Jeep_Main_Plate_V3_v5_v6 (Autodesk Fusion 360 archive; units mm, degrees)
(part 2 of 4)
sketch "Sketch16" plane through (0, 0, 15) normal (0, 0, 1) x axis (-1, 0, 0)
  line L1 (-8.4377, 5.259) -> (-11.4211, -2.2)
  line L2 (-10.5895, 5.2816) -> (-8.4377, 5.259)
  line L3 (2.418, 37.7236) -> (-10.5895, 5.2816)
  line L4 (3.9887, 36.2589) -> (2.418, 37.7236)
  line L5 (6.268, 41.9437) -> (3.9887, 36.2589)
  line L6 (18.9812, 36.8463) -> (6.268, 41.9437)
  line L7 (19.7255, 38.7027) -> (18.9812, 36.8463)
  line L8 (7.0123, 43.8) -> (19.7255, 38.7027)
  line L9 (-5, 43.8) -> (7.0123, 43.8)
  line L10 (-5, 42.6) -> (-5, 43.8)
  line L11 (0, 42.6) -> (-5, 42.6)
  line L12 (-57.3, 0) -> (-43.8, 0)
  line L13 (-60.8, 11) -> (-60.8, 3.5)
  line L14 (-62, 11) -> (-60.8, 11)
  line L15 (-62, 0.8) -> (-62, 11)
  line L16 (-11.4211, -2.2) -> (-59, -2.2)
  arc A1 centre (-49.0833, 49.2491) radius 49.5316 clockwise from (0, 42.6) to (-43.8, 0)
  arc A2 centre (-54.6577, 6.1423) radius 6.6865 clockwise from (-57.3, 0) to (-60.8, 3.5)
  arc A3 centre (-59, 0.8) radius 3 clockwise from (-59, -2.2) to (-62, 0.8)
extrude "Extrude16" cut of existing geometry blind -0.9
sketch "Sketch17" plane through (0, 0, 15) normal (0, 0, 1) x axis (-1, 0, 0)
  line L1 (-8.4377, 5.259) -> (-11.4211, -2.2)
  line L2 (-10.5895, 5.2816) -> (-8.4377, 5.259)
  line L3 (2.418, 37.7236) -> (-10.5895, 5.2816)
  line L4 (3.9887, 36.2589) -> (2.418, 37.7236)
  line L5 (6.268, 41.9437) -> (3.9887, 36.2589)
  line L6 (18.9812, 36.8463) -> (6.268, 41.9437)
  line L7 (19.7255, 38.7027) -> (18.9812, 36.8463)
  line L8 (7.0123, 43.8) -> (19.7255, 38.7027)
  line L9 (-5, 43.8) -> (7.0123, 43.8)
  line L10 (-5, 42.6) -> (-5, 43.8)
  line L11 (0, 42.6) -> (-5, 42.6)
  line L12 (-57.3, 0) -> (-43.8, 0)
  line L13 (-60.8, 11) -> (-60.8, 3.5)
  line L14 (-62, 11) -> (-60.8, 11)
  line L15 (-62, 0.8) -> (-62, 11)
  line L16 (-11.4211, -2.2) -> (-59, -2.2)
  arc A1 centre (-49.0833, 49.2491) radius 49.5316 clockwise from (0, 42.6) to (-43.8, 0)
  arc A2 centre (-54.6577, 6.1423) radius 6.6865 clockwise from (-57.3, 0) to (-60.8, 3.5)
  arc A3 centre (-59, 0.8) radius 3 clockwise from (-59, -2.2) to (-62, 0.8)
sketch "Sketch18" plane through (0, 0, 12) normal (0, 0, 1) x axis (-1, 0, 0)
  line L1 (2.7445, 0.6498) -> (17.4961, 37.4418)
  line L2 (3.9296, 0.6498) -> (2.7445, 0.6498)
  line L3 (4.3937, 0.4637) -> (3.9296, 0.6498)
  line L4 (18.9812, 36.8463) -> (4.3937, 0.4637)
  line L5 (17.4961, 37.4418) -> (18.9812, 36.8463)
  line L6 (10.0532, 18.8783) -> (17.4961, 37.4418)
  line L7 (15.3685, 18.8783) -> (10.0532, 18.8783)
  point P2 (17.4961, 37.4418)
  point P7 (17.4961, 37.4418)
  point P8 (10.0532, 18.8783)
  coincident P2 P7
  horizontal L7
  dimension "d118" distance P7 P8 = 20
extrude "Extrude17" cut sketch "Sketch18" profile of L1 L2 L3 L4 L7 against normal blind 10
sketch "Sketch19" plane through (0, 0, 2) normal (0, 0, 1) x axis (-1, 0, 0)
  line L1 (6.268, 41.9437) -> (17.4961, 37.4418)
  line L2 (3.9887, 36.2589) -> (6.268, 41.9437)
  line L3 (2.418, 37.7236) -> (3.9887, 36.2589)
  line L4 (-10.5895, 5.2816) -> (2.418, 37.7236)
  line L5 (-8.4377, 5.259) -> (-10.5895, 5.2816)
  line L6 (-11.4211, -2.2) -> (-8.4377, 5.259)
  line L7 (4.3937, 0.4637) -> (3.9296, 0.6498)
  line L8 (11.777, 18.8783) -> (4.3937, 0.4637)
  line L9 (10.0532, 18.8783) -> (11.777, 18.8783)
  line L10 (17.4961, 37.4418) -> (10.0532, 18.8783)
  arc A1 centre (-11.4211, 40.5698) radius 42.7698 clockwise from (3.9296, 0.6498) to (-11.4211, -2.2)
  arc A2 centre (-10.5418, 20.0938) radius 22.3111 clockwise from (6.4823, 5.6727) to (-11.4211, -2.2)
  point P15 (6.4823, 5.6727)
  point P8 (-11.4211, -2.2)
  point P14 (-11.4211, -2.2)
  coincident L8 P15
  coincident P8 P14
extrude "Extrude18" cut sketch "Sketch19" profile of A1 L7 L8 A2 against normal blind 10
fillet "Fillet3" radius 3
fillet "Fillet4" radius 4
fillet "Fillet5" radius 2
fillet "Fillet6" radius 7.25
sketch "Sketch20" plane through (0, 0, 2) normal (0, 0, 1) x axis (-1, 0, 0)
  line L1 (11.777, 18.8783) -> (6.4823, 5.6727)
  line L2 (10.0532, 18.8783) -> (11.777, 18.8783)
  line L3 (17.4961, 37.4418) -> (10.0532, 18.8783)
  line L4 (6.268, 41.9437) -> (17.4961, 37.4418)
  line L5 (3.9887, 36.2589) -> (6.268, 41.9437)
  line L6 (2.418, 37.7236) -> (3.9887, 36.2589)
  line L7 (-10.5895, 5.2816) -> (2.418, 37.7236)
  line L8 (-8.4377, 5.259) -> (-10.5895, 5.2816)
  line L9 (-10.4154, 0.3145) -> (-8.4377, 5.259)
  line L10 (-11.4211, -2.2) -> (-14.1293, -2.2)
  line L11 (3.9887, 36.2589) -> (-8.4377, 5.259)
  arc A1 centre (-10.5418, 20.0938) radius 22.3111 clockwise from (6.4823, 5.6727) to (-7.7545, -2.0425)
  arc A2 centre (-14.1293, 1.8) radius 4 clockwise from (-10.4154, 0.3145) to (-14.1293, -2.2)
  arc A3 centre (-11.4211, 40.5698) radius 42.7698 clockwise from (-7.7545, -2.0425) to (-11.4211, -2.2)
  point P12 (-8.4377, 5.259)
  point P18 (-8.4377, 5.259)
  point P9 (3.9887, 36.2589)
  point P19 (3.9887, 36.2589)
  coincident P12 P18
  coincident P9 P19
extrude "Extrude19" new body sketch "Sketch20" profile of L6 L7 L8 L11 along normal blind 13
sketch "Sketch21" plane through (0, 0, 15) normal (0, 0, 1) x axis (-1, 0, 0)
  line L1 (3.9887, 36.2589) -> (-8.4377, 5.259)
  line L2 (2.418, 37.7236) -> (3.9887, 36.2589)
  line L3 (-10.5895, 5.2816) -> (2.418, 37.7236)
  line L4 (-8.4377, 5.259) -> (-10.5895, 5.2816)
move "Move2"
sketch "Sketch22" plane through (0, 0, 34) normal (0, 0, 1) x axis (-1, 0, 0)
  line L1 (3.9887, 36.2589) -> (-8.4377, 5.259)
  line L2 (2.418, 37.7236) -> (3.9887, 36.2589)
  line L3 (-10.5895, 5.2816) -> (2.418, 37.7236)
  line L4 (-8.4377, 5.259) -> (-10.5895, 5.2816)
sketch "Sketch23" plane through (0, 0, 34) normal (0, 0, 1) x axis (-1, 0, 0)
  line L1 (3.9887, 36.2589) -> (-8.4377, 5.259)
  line L2 (2.418, 37.7236) -> (3.9887, 36.2589)
  line L3 (-10.5895, 5.2816) -> (2.418, 37.7236)
  line L4 (-8.4377, 5.259) -> (-10.5895, 5.2816)
  line L5 (7.0123, 49.1821) -> (1.6236, 35.7422)
  line L6 (18.9812, 36.8463) -> (6.268, 41.9437)
  line L7 (17.4961, 37.4418) -> (6.268, 41.9437)
  line L8 (4.4089, 42.689) -> (7.6114, 41.405)
  line L9 (6.268, 41.9437) -> (3.9887, 36.2589)
  line L10 (-15.0954, -5.9565) -> (-9.5797, 7.8002)
  line L11 (-12.7752, -5.5616) -> (-7.2156, 8.308)
  line L12 (-6.614, -0.9257) -> (-12.183, 1.3072)
  point P6 (1.6236, 35.7422)
  point P12 (7.6114, 41.405)
  point P13 (4.4089, 42.689)
  point P3 (3.9887, 36.2589)
  point P14 (3.9887, 36.2589)
  point P8 (6.268, 41.9437)
  point P15 (6.268, 41.9437)
  point P16 (-9.5797, 7.8002)
  point P18 (-7.2156, 8.308)
  point P20 (-12.183, 1.3072)
  point P21 (-6.614, -0.9257)
  coincident L3 P6
  parallel L3 L5
  coincident L6 P12
  coincident L5 P13
  perpendicular L5 L8
  coincident P3 P14
  coincident P8 P15
  coincident L3 P16
  parallel L3 L10
  coincident L1 P18
  parallel L1 L11
  coincident L10 P20
  dimension "d129" distance P20 P21 = 6
extrude "Extrude20" add sketch "Sketch23" profile of L1 L2 L3 L4 L5 L8 L9 L10 L11 L12 along normal blind 40
sketch "Sketch24" plane through (0, 0, 74) normal (0, 0, 1) x axis (-1, 0, 0)
  line L1 (-12.183, 1.3072) -> (4.4089, 42.689)
  line L2 (-10.3211, 0.5606) -> (-12.183, 1.3072)
  line L3 (3.9887, 36.2589) -> (-10.3211, 0.5606)
  line L4 (6.268, 41.9437) -> (3.9887, 36.2589)
  line L5 (4.4089, 42.689) -> (6.268, 41.9437)
remove_body "RemoveBody1"
sketch "Sketch25" plane through (0, 0, 2) normal (0, 0, 1) x axis (-1, 0, 0)
  line L1 (11.777, 18.8783) -> (6.4823, 5.6727)
  line L2 (10.0532, 18.8783) -> (11.777, 18.8783)
  line L3 (17.4961, 37.4418) -> (10.0532, 18.8783)
  line L4 (6.268, 41.9437) -> (17.4961, 37.4418)
  line L5 (3.9887, 36.2589) -> (6.268, 41.9437)
  line L6 (2.418, 37.7236) -> (3.9887, 36.2589)
  line L7 (-10.5895, 5.2816) -> (2.418, 37.7236)
  line L8 (-8.4377, 5.259) -> (-10.5895, 5.2816)
  line L9 (-10.4154, 0.3145) -> (-8.4377, 5.259)
  line L10 (-11.4211, -2.2) -> (-14.1293, -2.2)
  line L11 (-8.4377, 5.259) -> (-11.4211, -2.2)
  line L12 (8.3111, 47.134) -> (-9.9294, 1.5295)
  line L13 (3.9887, 36.2589) -> (-10.3211, 0.5606)
  line L14 (3.9887, 36.2589) -> (-8.4377, 5.259)
  line L15 (-11.7486, -3.0312) -> (-6.1781, 10.8961)
  line L16 (-25.6775, -38.0332) -> (7.6802, 45.5567)
  arc A1 centre (-10.5418, 20.0938) radius 22.3111 clockwise from (6.4823, 5.6727) to (-7.7545, -2.0425)
  arc A2 centre (-14.1293, 1.8) radius 4 clockwise from (-10.4154, 0.3145) to (-14.1293, -2.2)
  arc A3 centre (-11.4211, 40.5698) radius 42.7698 clockwise from (-7.7545, -2.0425) to (-11.4211, -2.2)
  point P20 (-9.9294, 1.5295)
  point P26 (-6.1781, 10.8961)
  point P28 (7.6802, 45.5567)
  point P27 (-11.7486, -3.0312)
  point P29 (-25.6775, -38.0332)
  midpoint L11 P20
  coincident L13 P26
  coincident L12 P28
  dimension "d132" distance P26 P27 = 15
  dimension "d133" distance P28 P29 = 90
split "Split1"
move "Move3"
sketch "Sketch26" plane through (0, 0, 0) normal (0, 1, 0) x axis (1, 0, 0)
  line L1 (-8.7, 0) -> (-4.2, 0)
  horizontal L1
sketch "Sketch27" plane through (0, 0, 0) normal (0, 0, 1) x axis (1, 0, 0)
  line L1 (-13.3689, -43.8) -> (-4.6131, -43.8)
  line L2 (-13.3689, -41.9403) -> (-13.3689, -43.8)
  line L3 (-4.6131, -41.9403) -> (-13.3689, -41.9403)
  line L4 (-4.6131, -43.8) -> (-4.6131, -41.9403)
  line L5 (5, -43.8) -> (-7.0123, -43.8)
  line L6 (5, -43.8) -> (-5.613, -43.8)
  point P2 (-4.6131, -43.8)
  horizontal L1
  vertical L2
  horizontal L3
  vertical L4
  coincident P2 L5
move "Move4"
sketch "Sketch28" plane through (0, 0, 2) normal (0, 0, 1) x axis (-1, 0, 0)
  line L1 (3.9749, 36.2718) -> (-11.3778, -2.2)
  line L2 (2.418, 37.7236) -> (3.9749, 36.2718)
  line L3 (-10.5895, 5.2816) -> (2.418, 37.7236)
  line L4 (-8.4377, 5.259) -> (-10.5895, 5.2816)
  line L5 (-10.4154, 0.3145) -> (-8.4377, 5.259)
  line L6 (-11.4211, -2.2) -> (-14.1293, -2.2)
  arc A1 centre (-14.1293, 1.8) radius 4 clockwise from (-10.4154, 0.3145) to (-14.1293, -2.2)
  arc A2 centre (-11.4211, 40.5698) radius 42.7698 clockwise from (-11.3778, -2.2) to (-11.4211, -2.2)
sketch "Sketch29" plane through (0, 0, 0) normal (0, 0, 1) x axis (1, 0, 0)
  line L1 (-17.0909, -43.8) -> (-4.2862, -43.8)
  line L2 (-17.0909, -41.9413) -> (-17.0909, -43.8)
  line L3 (-4.2862, -41.9413) -> (-17.0909, -41.9413)
  line L4 (-4.2862, -43.8) -> (-4.2862, -41.9413)
  line L5 (5, -43.8) -> (-5.613, -43.8)
  line L6 (-5.613, -43.8) -> (5, -43.8)
  line L7 (-17.8562, -43.8) -> (-3.9146, -43.8)
  line L8 (-17.8562, -41.9413) -> (-17.8562, -43.8)
  line L9 (-3.9146, -41.9413) -> (-17.8562, -41.9413)
  line L10 (-3.9146, -43.8) -> (-3.9146, -41.9413)
  point P2 (-4.2862, -43.8)
  point P10 (-3.9146, -43.8)
  horizontal L1
  vertical L2
  horizontal L3
  vertical L4
  coincident P2 L5
  horizontal L7
  vertical L8
  horizontal L9
  vertical L10
  coincident L5 P10
sketch "Sketch30" plane through (0, 0, 0) normal (0, 0, 1) x axis (1, 0, 0)
extrude "Extrude21" add sketch "Sketch29" profile of L1 L2 L3 L4 L5 L6 L7 L9 along normal blind 15
sketch "Sketch31" plane through (0, 0, 0) normal (0, 0, 1) x axis (1, 0, 0)
  line L1 (-2.418, -37.7236) -> (-3.9887, -36.2589)
  line L2 (-3.9887, -36.2589) -> (-2.418, -37.7236)
  line L3 (-14.5557, -26.4051) -> (-3.5854, -36.6351)
  line L4 (-15.267, -41.9413) -> (-10.534, -30.1553)
  line L5 (-6.268, -41.9437) -> (-15.267, -41.9413)
  line L6 (-3.9887, -36.2589) -> (-6.268, -41.9437)
  point P6 (-3.5854, -36.6351)
  point P9 (-10.534, -30.1553)
  point P8 (-15.267, -41.9413)
  point P10 (-15.267, -41.9413)
  point P11 (-6.268, -41.9437)
  point P12 (-6.268, -41.9437)
  point P5 (-3.9887, -36.2589)
  point P13 (-3.9887, -36.2589)
  point P7 (-14.5557, -26.4051)
  coincident L1 P6
  coincident L3 P9
  coincident P8 P10
  coincident P11 P12
  coincident P5 P13
  dimension "d136" distance P6 P7 = 15
extrude "Extrude22" add sketch "Sketch31" profile of L3 L4 L5 L6 along normal blind 15
sketch "Sketch32" plane through (0, 0, 0) normal (0, 0, 1) x axis (1, 0, 0)
  line L1 (10.5895, -5.2816) -> (8.4377, -5.259)
  line L2 (8.4377, -5.259) -> (10.5895, -5.2816)
  line L3 (-4.0781, -5.259) -> (9.8776, -5.2741)
  line L4 (2.3778, 2.2) -> (-0.6003, -5.2628)
  line L5 (59, 2.2) -> (11.4211, 2.2)
  line L6 (14.5973, 2.2) -> (2.3778, 2.2)
  line L7 (10.5895, -5.2816) -> (14.5973, 2.2)
  point P6 (9.8776, -5.2741)
  point P9 (-0.6003, -5.2628)
  point P8 (2.3778, 2.2)
  point P10 (2.3778, 2.2)
  point P13 (14.5973, 2.2)
  point P4 (10.5895, -5.2816)
  point P14 (10.5895, -5.2816)
  coincident L1 P6
  coincident L3 P9
  coincident P8 P10
  coincident L5 P13
  coincident P4 P14
extrude "Extrude23" add sketch "Sketch32" along normal blind 15
sketch "Sketch33" plane through (0, 0, 15) normal (0, 0, 1) x axis (-1, 0, 0)
  line L1 (2.418, 37.7236) -> (-10.5895, 5.2816)
  line L2 (3.9749, 36.2718) -> (2.418, 37.7236)
  line L3 (6.2374, 41.9413) -> (3.9749, 36.2718)
  line L4 (6.267, 41.9413) -> (6.2374, 41.9413)
  line L5 (3.9887, 36.2589) -> (6.267, 41.9413)
  line L6 (10.534, 30.1553) -> (3.9887, 36.2589)
  line L7 (12.9861, 36.2614) -> (10.534, 30.1553)
  line L8 (12.9887, 36.2589) -> (12.9861, 36.2614)
  line L9 (15.267, 41.9413) -> (12.9887, 36.2589)
  line L10 (15.274, 41.9413) -> (15.267, 41.9413)
  line L11 (27.9812, 36.8463) -> (15.274, 41.9413)
  line L12 (17.3111, 43.2793) -> (26.8692, 39.447)
  line L13 (17.0909, 43.8) -> (17.0909, 43.3634)
  line L14 (-5, 43.8) -> (17.0909, 43.8)
  line L15 (-5, 42.6) -> (-5, 43.8)
  line L16 (0, 42.6) -> (-5, 42.6)
  line L17 (-57.3, 0) -> (-43.8, 0)
  line L18 (-60.8, 11) -> (-60.8, 3.5)
  line L19 (-62, 11) -> (-60.8, 11)
  line L20 (-62, 0.8) -> (-62, 11)
  line L21 (-14.1293, -2.2) -> (-59, -2.2)
  line L22 (-2.3778, -2.2) -> (-14.1293, -2.2)
  line L23 (0.6003, 5.2628) -> (-2.3778, -2.2)
  line L24 (-9.8776, 5.2741) -> (0.6003, 5.2628)
  line L25 (-10.5895, 5.2816) -> (-9.8776, 5.2741)
  line L26 (9.0671, 46.5544) -> (18.3592, 42.859)
  arc A1 centre (26.1249, 37.5906) radius 2 clockwise from (26.8692, 39.447) to (27.9812, 36.8463)
  arc A2 centre (14.613, 36.55) radius 7.25 clockwise from (17.0909, 43.3634) to (17.3111, 43.2793)
  arc A3 centre (-49.0833, 49.2491) radius 49.5316 clockwise from (0, 42.6) to (-43.8, 0)
  arc A4 centre (-54.6577, 6.1423) radius 6.6865 clockwise from (-57.3, 0) to (-60.8, 3.5)
  arc A5 centre (-59, 0.8) radius 3 clockwise from (-59, -2.2) to (-62, 0.8)
  point P37 (18.3592, 42.859)
  point P38 (9.0671, 46.5544)
  coincident L12 P37
  dimension "d141" distance P37 P38 = 10
extrude "Extrude24" cut sketch "Sketch33" profile of L13 L14 L26 against normal blind 23.5
sketch "Sketch34" plane through (0, 0, 2) normal (0, 0, 1) x axis (-1, 0, 0)
  line L1 (10.534, 30.1553) -> (12.9861, 36.2614)
  line L2 (0.6003, 5.2628) -> (10.534, 30.1553)
  line L3 (-2.3778, -2.2) -> (0.6003, 5.2628)
  line L4 (20.777, 18.8783) -> (15.4823, 5.6727)
  line L5 (19.0532, 18.8783) -> (20.777, 18.8783)
  line L6 (26.4961, 37.4418) -> (19.0532, 18.8783)
  line L7 (15.274, 41.9413) -> (26.4961, 37.4418)
  line L8 (15.267, 41.9413) -> (15.274, 41.9413)
  line L9 (12.9887, 36.2589) -> (15.267, 41.9413)
  line L10 (12.9861, 36.2614) -> (12.9887, 36.2589)
  arc A1 centre (-2.4211, 40.5698) radius 42.7698 clockwise from (1.2455, -2.0425) to (-2.3778, -2.2)
  arc A2 centre (-1.5418, 20.0938) radius 22.3111 clockwise from (15.4823, 5.6727) to (1.2455, -2.0425)
fillet "Fillet7" radius 1
fillet "Fillet8" radius 8.5
sketch "Sketch35" plane through (0, 0, 0) normal (0, 0, 1) x axis (1, 0, 0)
  line L1 (-0.6003, -5.2628) -> (8.4377, -5.259)
  line L2 (-10.534, -30.1553) -> (-0.6003, -5.2628)
  line L3 (-3.9887, -36.2589) -> (-10.534, -30.1553)
  line L4 (8.4377, -5.259) -> (-3.9887, -36.2589)
  point P2 (8.4377, -5.259)
  point P4 (8.4377, -5.259)
  point P3 (-0.6003, -5.2628)
  point P5 (-0.6003, -5.2628)
  point P6 (-10.534, -30.1553)
  point P7 (-10.534, -30.1553)
  point P8 (-3.9887, -36.2589)
  point P9 (-3.9887, -36.2589)
  coincident P2 P4
  coincident P3 P5
  coincident P6 P7
  coincident P8 P9
extrude "Extrude25" add sketch "Sketch35" along normal blind 2
sketch "Sketch36" plane through (0, 0, 15) normal (0, 0, 1) x axis (-1, 0, 0)
  line L1 (-5, 43.8) -> (14.4017, 43.8)
  line L2 (-5, 42.6) -> (-5, 43.8)
  line L3 (0, 42.6) -> (-5, 42.6)
  line L4 (-57.3, 0) -> (-43.8, 0)
  line L5 (-60.8, 11) -> (-60.8, 3.5)
  line L6 (-62, 11) -> (-60.8, 11)
  line L7 (-62, 0.8) -> (-62, 11)
  line L8 (-14.1293, -2.2) -> (-59, -2.2)
  line L9 (-3.0554, -2.2) -> (-14.1293, -2.2)
  line L10 (0.6003, 5.2628) -> (-2.1266, -1.5706)
  line L11 (-9.8776, 5.2741) -> (0.6003, 5.2628)
  line L12 (-10.5895, 5.2816) -> (-9.8776, 5.2741)
  line L13 (2.418, 37.7236) -> (-10.5895, 5.2816)
  line L14 (3.9749, 36.2718) -> (2.418, 37.7236)
  line L15 (6.2374, 41.9413) -> (3.9749, 36.2718)
  line L16 (6.267, 41.9413) -> (6.2374, 41.9413)
  line L17 (3.9887, 36.2589) -> (6.267, 41.9413)
  line L18 (10.534, 30.1553) -> (3.9887, 36.2589)
  line L19 (12.9861, 36.2614) -> (10.534, 30.1553)
  line L20 (12.9887, 36.2589) -> (12.9861, 36.2614)
  line L21 (15.267, 41.9413) -> (12.9887, 36.2589)
  line L22 (15.274, 41.9413) -> (15.267, 41.9413)
  line L23 (27.9812, 36.8463) -> (15.274, 41.9413)
  line L24 (17.3111, 43.2793) -> (26.8692, 39.447)
  arc A1 centre (14.4017, 35.3) radius 8.5 clockwise from (14.4017, 43.8) to (17.0909, 43.3634)
  arc A2 centre (-49.0833, 49.2491) radius 49.5316 clockwise from (0, 42.6) to (-43.8, 0)
  arc A3 centre (-54.6577, 6.1423) radius 6.6865 clockwise from (-57.3, 0) to (-60.8, 3.5)
  arc A4 centre (-59, 0.8) radius 3 clockwise from (-59, -2.2) to (-62, 0.8)
  arc A5 centre (-3.0554, -1.2) radius 1 clockwise from (-2.1266, -1.5706) to (-3.0554, -2.2)
  arc A6 centre (26.1249, 37.5906) radius 2 clockwise from (26.8692, 39.447) to (27.9812, 36.8463)
  arc A7 centre (14.613, 36.55) radius 7.25 clockwise from (17.0909, 43.3634) to (17.3111, 43.2793)
sketch "Sketch37" plane through (0, 0, 15) normal (0, 0, 1) x axis (-1, 0, 0)
  line L1 (-5, 43.8) -> (14.4017, 43.8)
  line L2 (-5, 42.6) -> (-5, 43.8)
  line L3 (0, 42.6) -> (-5, 42.6)
  line L4 (-57.3, 0) -> (-43.8, 0)
  line L5 (-60.8, 11) -> (-60.8, 3.5)
  line L6 (-62, 11) -> (-60.8, 11)
  line L7 (-62, 0.8) -> (-62, 11)
  line L8 (-14.1293, -2.2) -> (-59, -2.2)
  line L9 (-3.0554, -2.2) -> (-14.1293, -2.2)
  line L10 (0.6003, 5.2628) -> (-2.1266, -1.5706)
  line L11 (-9.8776, 5.2741) -> (0.6003, 5.2628)
  line L12 (-10.5895, 5.2816) -> (-9.8776, 5.2741)
  line L13 (2.418, 37.7236) -> (-10.5895, 5.2816)
  line L14 (3.9749, 36.2718) -> (2.418, 37.7236)
  line L15 (6.2374, 41.9413) -> (3.9749, 36.2718)
  line L16 (6.267, 41.9413) -> (6.2374, 41.9413)
  line L17 (3.9887, 36.2589) -> (6.267, 41.9413)
  line L18 (10.534, 30.1553) -> (3.9887, 36.2589)
  line L19 (12.9861, 36.2614) -> (10.534, 30.1553)
  line L20 (12.9887, 36.2589) -> (12.9861, 36.2614)
  line L21 (15.267, 41.9413) -> (12.9887, 36.2589)
  line L22 (15.274, 41.9413) -> (15.267, 41.9413)
  line L23 (27.9812, 36.8463) -> (15.274, 41.9413)
  line L24 (17.3111, 43.2793) -> (26.8692, 39.447)
  arc A1 centre (14.4017, 35.3) radius 8.5 clockwise from (14.4017, 43.8) to (17.0909, 43.3634)
  arc A2 centre (-49.0833, 49.2491) radius 49.5316 clockwise from (0, 42.6) to (-43.8, 0)
  arc A3 centre (-54.6577, 6.1423) radius 6.6865 clockwise from (-57.3, 0) to (-60.8, 3.5)
  arc A4 centre (-59, 0.8) radius 3 clockwise from (-59, -2.2) to (-62, 0.8)
  arc A5 centre (-3.0554, -1.2) radius 1 clockwise from (-2.1266, -1.5706) to (-3.0554, -2.2)
  arc A6 centre (26.1249, 37.5906) radius 2 clockwise from (26.8692, 39.447) to (27.9812, 36.8463)
  arc A7 centre (14.613, 36.55) radius 7.25 clockwise from (17.0909, 43.3634) to (17.3111, 43.2793)
sketch "Sketch38" plane through (0, 0, 15) normal (0, 0, 1) x axis (-1, 0, 0)
  line L1 (-5, 43.8) -> (14.4017, 43.8)
  line L2 (-5, 42.6) -> (-5, 43.8)
  line L3 (0, 42.6) -> (-5, 42.6)
  line L4 (-57.3, 0) -> (-43.8, 0)
  line L5 (-60.8, 11) -> (-60.8, 3.5)
  line L6 (-62, 11) -> (-60.8, 11)
  line L7 (-62, 0.8) -> (-62, 11)
  line L8 (-14.1293, -2.2) -> (-59, -2.2)
  line L9 (-3.0554, -2.2) -> (-14.1293, -2.2)
  line L10 (0.6003, 5.2628) -> (-2.1266, -1.5706)
  line L11 (-9.8776, 5.2741) -> (0.6003, 5.2628)
  line L12 (-10.5895, 5.2816) -> (-9.8776, 5.2741)
  line L13 (2.418, 37.7236) -> (-10.5895, 5.2816)
  line L14 (3.9749, 36.2718) -> (2.418, 37.7236)
  line L15 (6.2374, 41.9413) -> (3.9749, 36.2718)
  line L16 (6.267, 41.9413) -> (6.2374, 41.9413)
  line L17 (3.9887, 36.2589) -> (6.267, 41.9413)
  line L18 (10.534, 30.1553) -> (3.9887, 36.2589)
  line L19 (12.9861, 36.2614) -> (10.534, 30.1553)
  line L20 (12.9887, 36.2589) -> (12.9861, 36.2614)
  line L21 (15.267, 41.9413) -> (12.9887, 36.2589)
  line L22 (15.274, 41.9413) -> (15.267, 41.9413)
  line L23 (27.9812, 36.8463) -> (15.274, 41.9413)
  line L24 (17.3111, 43.2793) -> (26.8692, 39.447)
  arc A1 centre (14.4017, 35.3) radius 8.5 clockwise from (14.4017, 43.8) to (17.0909, 43.3634)
  arc A2 centre (-49.0833, 49.2491) radius 49.5316 clockwise from (0, 42.6) to (-43.8, 0)
  arc A3 centre (-54.6577, 6.1423) radius 6.6865 clockwise from (-57.3, 0) to (-60.8, 3.5)
  arc A4 centre (-59, 0.8) radius 3 clockwise from (-59, -2.2) to (-62, 0.8)
  arc A5 centre (-3.0554, -1.2) radius 1 clockwise from (-2.1266, -1.5706) to (-3.0554, -2.2)
  arc A6 centre (26.1249, 37.5906) radius 2 clockwise from (26.8692, 39.447) to (27.9812, 36.8463)
  arc A7 centre (14.613, 36.55) radius 7.25 clockwise from (17.0909, 43.3634) to (17.3111, 43.2793)
sketch "Sketch39" plane through (10.9473, -4.3893, 0) normal (-0.9282, 0.3721, 0) x axis (-0.3721, -0.9282, 0)
  line L1 (35.9139, 2) -> (0.9613, 2)
  line L2 (35.9139, 15) -> (35.9139, 2)
  line L3 (0.9613, 15) -> (35.9139, 15)
  line L4 (0.9613, 2) -> (0.9613, 15)
sketch "Sketch40" plane through (0, 0, 15) normal (0, 0, 1) x axis (-1, 0, 0)
  line L1 (-5, 43.8) -> (14.4017, 43.8)
  line L2 (-5, 42.6) -> (-5, 43.8)
  line L3 (0, 42.6) -> (-5, 42.6)
  line L4 (-57.3, 0) -> (-43.8, 0)
  line L5 (-60.8, 11) -> (-60.8, 3.5)
  line L6 (-62, 11) -> (-60.8, 11)
  line L7 (-62, 0.8) -> (-62, 11)
  line L8 (-14.1293, -2.2) -> (-59, -2.2)
  line L9 (-3.0554, -2.2) -> (-14.1293, -2.2)
  line L10 (0.6003, 5.2628) -> (-2.1266, -1.5706)
  line L11 (-9.8776, 5.2741) -> (0.6003, 5.2628)
  line L12 (-10.5895, 5.2816) -> (-9.8776, 5.2741)
  line L13 (2.418, 37.7236) -> (-10.5895, 5.2816)
  line L14 (3.9749, 36.2718) -> (2.418, 37.7236)
  line L15 (6.2374, 41.9413) -> (3.9749, 36.2718)
  line L16 (6.267, 41.9413) -> (6.2374, 41.9413)
  line L17 (3.9887, 36.2589) -> (6.267, 41.9413)
  line L18 (10.534, 30.1553) -> (3.9887, 36.2589)
  line L19 (12.9861, 36.2614) -> (10.534, 30.1553)
  line L20 (12.9887, 36.2589) -> (12.9861, 36.2614)
  line L21 (15.267, 41.9413) -> (12.9887, 36.2589)
  line L22 (15.274, 41.9413) -> (15.267, 41.9413)
  line L23 (27.9812, 36.8463) -> (15.274, 41.9413)
  line L24 (17.3111, 43.2793) -> (26.8692, 39.447)
  arc A1 centre (14.4017, 35.3) radius 8.5 clockwise from (14.4017, 43.8) to (17.0909, 43.3634)
  arc A2 centre (-49.0833, 49.2491) radius 49.5316 clockwise from (0, 42.6) to (-43.8, 0)
  arc A3 centre (-54.6577, 6.1423) radius 6.6865 clockwise from (-57.3, 0) to (-60.8, 3.5)
  arc A4 centre (-59, 0.8) radius 3 clockwise from (-59, -2.2) to (-62, 0.8)
  arc A5 centre (-3.0554, -1.2) radius 1 clockwise from (-2.1266, -1.5706) to (-3.0554, -2.2)
  arc A6 centre (26.1249, 37.5906) radius 2 clockwise from (26.8692, 39.447) to (27.9812, 36.8463)
  arc A7 centre (14.613, 36.55) radius 7.25 clockwise from (17.0909, 43.3634) to (17.3111, 43.2793)
sketch "Sketch41" plane through (0, 0, 15) normal (0, 0, 1) x axis (-1, 0, 0)
  line L1 (-5, 43.8) -> (14.4017, 43.8)
  line L2 (-5, 42.6) -> (-5, 43.8)
  line L3 (0, 42.6) -> (-5, 42.6)
  line L4 (-57.3, 0) -> (-43.8, 0)
  line L5 (-60.8, 11) -> (-60.8, 3.5)
  line L6 (-62, 11) -> (-60.8, 11)
  line L7 (-62, 0.8) -> (-62, 11)
  line L8 (-14.1293, -2.2) -> (-59, -2.2)
  line L9 (-3.0554, -2.2) -> (-14.1293, -2.2)
  line L10 (0.6003, 5.2628) -> (-2.1266, -1.5706)
  line L11 (-9.8776, 5.2741) -> (0.6003, 5.2628)
  line L12 (-10.5895, 5.2816) -> (-9.8776, 5.2741)
  line L13 (2.418, 37.7236) -> (-10.5895, 5.2816)
  line L14 (3.9749, 36.2718) -> (2.418, 37.7236)
  line L15 (6.2374, 41.9413) -> (3.9749, 36.2718)
  line L16 (6.267, 41.9413) -> (6.2374, 41.9413)
  line L17 (3.9887, 36.2589) -> (6.267, 41.9413)
  line L18 (10.534, 30.1553) -> (3.9887, 36.2589)
  line L19 (12.9861, 36.2614) -> (10.534, 30.1553)
  line L20 (12.9887, 36.2589) -> (12.9861, 36.2614)
  line L21 (15.267, 41.9413) -> (12.9887, 36.2589)
  line L22 (15.274, 41.9413) -> (15.267, 41.9413)
  line L23 (27.9812, 36.8463) -> (15.274, 41.9413)
  line L24 (17.3111, 43.2793) -> (26.8692, 39.447)
  arc A1 centre (14.4017, 35.3) radius 8.5 clockwise from (14.4017, 43.8) to (17.0909, 43.3634)
  arc A2 centre (-49.0833, 49.2491) radius 49.5316 clockwise from (0, 42.6) to (-43.8, 0)
  arc A3 centre (-54.6577, 6.1423) radius 6.6865 clockwise from (-57.3, 0) to (-60.8, 3.5)
  arc A4 centre (-59, 0.8) radius 3 clockwise from (-59, -2.2) to (-62, 0.8)
  arc A5 centre (-3.0554, -1.2) radius 1 clockwise from (-2.1266, -1.5706) to (-3.0554, -2.2)
  arc A6 centre (26.1249, 37.5906) radius 2 clockwise from (26.8692, 39.447) to (27.9812, 36.8463)
  arc A7 centre (14.613, 36.55) radius 7.25 clockwise from (17.0909, 43.3634) to (17.3111, 43.2793)
sketch "Sketch42" plane through (0, 0, 15) normal (0, 0, 1) x axis (-1, 0, 0)
  line L1 (-5, 43.8) -> (14.4017, 43.8)
  line L2 (-5, 42.6) -> (-5, 43.8)
  line L3 (0, 42.6) -> (-5, 42.6)
  line L4 (-57.3, 0) -> (-43.8, 0)
  line L5 (-60.8, 11) -> (-60.8, 3.5)
  line L6 (-62, 11) -> (-60.8, 11)
  line L7 (-62, 0.8) -> (-62, 11)
  line L8 (-14.1293, -2.2) -> (-59, -2.2)
  line L9 (-3.0554, -2.2) -> (-14.1293, -2.2)
  line L10 (0.6003, 5.2628) -> (-2.1266, -1.5706)
  line L11 (-9.8776, 5.2741) -> (0.6003, 5.2628)
  line L12 (-10.5895, 5.2816) -> (-9.8776, 5.2741)
  line L13 (2.418, 37.7236) -> (-10.5895, 5.2816)
  line L14 (3.9749, 36.2718) -> (2.418, 37.7236)
  line L15 (6.2374, 41.9413) -> (3.9749, 36.2718)
  line L16 (6.267, 41.9413) -> (6.2374, 41.9413)
  line L17 (3.9887, 36.2589) -> (6.267, 41.9413)
  line L18 (10.534, 30.1553) -> (3.9887, 36.2589)
  line L19 (12.9861, 36.2614) -> (10.534, 30.1553)
  line L20 (12.9887, 36.2589) -> (12.9861, 36.2614)
  line L21 (15.267, 41.9413) -> (12.9887, 36.2589)
  line L22 (15.274, 41.9413) -> (15.267, 41.9413)
  line L23 (27.9812, 36.8463) -> (15.274, 41.9413)
  line L24 (17.3111, 43.2793) -> (26.8692, 39.447)
  arc A1 centre (14.4017, 35.3) radius 8.5 clockwise from (14.4017, 43.8) to (17.0909, 43.3634)
  arc A2 centre (-49.0833, 49.2491) radius 49.5316 clockwise from (0, 42.6) to (-43.8, 0)
  arc A3 centre (-54.6577, 6.1423) radius 6.6865 clockwise from (-57.3, 0) to (-60.8, 3.5)
  arc A4 centre (-59, 0.8) radius 3 clockwise from (-59, -2.2) to (-62, 0.8)
  arc A5 centre (-3.0554, -1.2) radius 1 clockwise from (-2.1266, -1.5706) to (-3.0554, -2.2)
  arc A6 centre (26.1249, 37.5906) radius 2 clockwise from (26.8692, 39.447) to (27.9812, 36.8463)
  arc A7 centre (14.613, 36.55) radius 7.25 clockwise from (17.0909, 43.3634) to (17.3111, 43.2793)
sketch "Sketch43" plane through (0, 0, 15) normal (0, 0, 1) x axis (-1, 0, 0)
  line L1 (-5, 43.8) -> (14.4017, 43.8)
  line L2 (-5, 42.6) -> (-5, 43.8)
  line L3 (0, 42.6) -> (-5, 42.6)
  line L4 (-57.3, 0) -> (-43.8, 0)
  line L5 (-60.8, 11) -> (-60.8, 3.5)
  line L6 (-62, 11) -> (-60.8, 11)
  line L7 (-62, 0.8) -> (-62, 11)
  line L8 (-14.1293, -2.2) -> (-59, -2.2)
  line L9 (-3.0554, -2.2) -> (-14.1293, -2.2)
  line L10 (0.6003, 5.2628) -> (-2.1266, -1.5706)
  line L11 (-9.8776, 5.2741) -> (0.6003, 5.2628)
  line L12 (-10.5895, 5.2816) -> (-9.8776, 5.2741)
  line L13 (2.418, 37.7236) -> (-10.5895, 5.2816)
  line L14 (3.9749, 36.2718) -> (2.418, 37.7236)
  line L15 (6.2374, 41.9413) -> (3.9749, 36.2718)
  line L16 (6.267, 41.9413) -> (6.2374, 41.9413)
  line L17 (3.9887, 36.2589) -> (6.267, 41.9413)
  line L18 (10.534, 30.1553) -> (3.9887, 36.2589)
  line L19 (12.9861, 36.2614) -> (10.534, 30.1553)
  line L20 (12.9887, 36.2589) -> (12.9861, 36.2614)
  line L21 (15.267, 41.9413) -> (12.9887, 36.2589)
  line L22 (15.274, 41.9413) -> (15.267, 41.9413)
  line L23 (27.9812, 36.8463) -> (15.274, 41.9413)
  line L24 (17.3111, 43.2793) -> (26.8692, 39.447)
  line L25 (5.1224, 5.2741) -> (-9.8776, 5.2741)
  line L26 (11.5275, 20.7345) -> (2.418, 37.7236)
  line L27 (21.6953, 37.7236) -> (2.418, 37.7236)
  line L28 (6.7923, 10.9964) -> (-10.5895, 5.2816)
  line L29 (7.7077, 5.2816) -> (-10.5895, 5.2816)
  line L30 (-0.7632, 1.8461) -> (12.4608, 34.9534)
  arc A1 centre (14.4017, 35.3) radius 8.5 clockwise from (14.4017, 43.8) to (17.0909, 43.3634)
  arc A2 centre (-49.0833, 49.2491) radius 49.5316 clockwise from (0, 42.6) to (-43.8, 0)
  arc A3 centre (-54.6577, 6.1423) radius 6.6865 clockwise from (-57.3, 0) to (-60.8, 3.5)
  arc A4 centre (-59, 0.8) radius 3 clockwise from (-59, -2.2) to (-62, 0.8)
  arc A5 centre (-3.0554, -1.2) radius 1 clockwise from (-2.1266, -1.5706) to (-3.0554, -2.2)
  arc A6 centre (26.1249, 37.5906) radius 2 clockwise from (26.8692, 39.447) to (27.9812, 36.8463)
  arc A7 centre (14.613, 36.55) radius 7.25 clockwise from (17.0909, 43.3634) to (17.3111, 43.2793)
  point P23 (-9.8776, 5.2741)
  point P40 (-9.8776, 5.2741)
  point P25 (2.418, 37.7236)
  point P42 (2.418, 37.7236)
  point P24 (-10.5895, 5.2816)
  point P45 (-10.5895, 5.2816)
  point P48 (12.4608, 34.9534)
  point P49 (-0.7632, 1.8461)
  coincident P23 P40
  horizontal L25
  coincident P25 P42
  horizontal L27
  coincident P24 P45
  horizontal L29
  coincident L19 P48
  midpoint L10 P49
  dimension "d150" angle L26 L27 = 61.8
  dimension "d151" angle L28 L29 = 18.2
extrude "Extrude26" add sketch "Sketch43" profile of L10 L11 L12 L14 L15 L16 L17 L18 L19 L26 L28 L30 against normal blind 13.5
sketch "Sketch44" plane through (0, 0, 15) normal (0, 0, 1) x axis (-1, 0, 0)
  line L1 (-5, 43.8) -> (14.4017, 43.8)
  line L2 (-5, 42.6) -> (-5, 43.8)
  line L3 (0, 42.6) -> (-5, 42.6)
  line L4 (-57.3, 0) -> (-43.8, 0)
  line L5 (-60.8, 11) -> (-60.8, 3.5)
  line L6 (-62, 11) -> (-60.8, 11)
  line L7 (-62, 0.8) -> (-62, 11)
  line L8 (-14.1293, -2.2) -> (-59, -2.2)
  line L9 (-3.0554, -2.2) -> (-14.1293, -2.2)
  line L10 (-0.7632, 1.8461) -> (-2.1266, -1.5706)
  line L11 (2.3021, 9.5201) -> (-0.7632, 1.8461)
  line L12 (-10.5895, 5.2816) -> (2.3021, 9.5201)
  line L13 (2.418, 37.7236) -> (-10.5895, 5.2816)
  line L14 (8.8076, 25.8072) -> (2.418, 37.7236)
  line L15 (12.4608, 34.9534) -> (8.8076, 25.8072)
  line L16 (12.9861, 36.2614) -> (12.4608, 34.9534)
  line L17 (12.9887, 36.2589) -> (12.9861, 36.2614)
  line L18 (15.267, 41.9413) -> (12.9887, 36.2589)
  line L19 (15.274, 41.9413) -> (15.267, 41.9413)
  line L20 (27.9812, 36.8463) -> (15.274, 41.9413)
  line L21 (17.3111, 43.2793) -> (26.8692, 39.447)
  line L22 (-1.184, 48.54) -> (18.0582, 40.8249)
  arc A1 centre (14.4017, 35.3) radius 8.5 clockwise from (14.4017, 43.8) to (17.0909, 43.3634)
  arc A2 centre (-49.0833, 49.2491) radius 49.5316 clockwise from (0, 42.6) to (-43.8, 0)
  arc A3 centre (-54.6577, 6.1423) radius 6.6865 clockwise from (-57.3, 0) to (-60.8, 3.5)
  arc A4 centre (-59, 0.8) radius 3 clockwise from (-59, -2.2) to (-62, 0.8)
  arc A5 centre (-3.0554, -1.2) radius 1 clockwise from (-2.1266, -1.5706) to (-3.0554, -2.2)
  arc A6 centre (26.1249, 37.5906) radius 2 clockwise from (26.8692, 39.447) to (27.9812, 36.8463)
  arc A7 centre (14.613, 36.55) radius 7.25 clockwise from (17.0909, 43.3634) to (17.3111, 43.2793)
  point P37 (18.0582, 40.8249)
  coincident L20 P37
  parallel L20 L22
sketch "Sketch45" plane through (0, 0, 12) normal (0, 0, 1) x axis (-1, 0, 0)
  line L1 (21.9798, 21.8783) -> (20.256, 21.8783)
  line L2 (27.9812, 36.8463) -> (21.9798, 21.8783)
  line L3 (26.4961, 37.4418) -> (27.9812, 36.8463)
  line L4 (20.256, 21.8783) -> (26.4961, 37.4418)
delete_face "DeleteFace1"
extrude "Extrude27" add of existing geometry blind 1
fillet "Fillet9" radius 2
sketch "Sketch46" plane through (0, 0, 0) normal (0, 0, -1) x axis (1, 0, 0)
  line L1 (63, 11) -> (63, -0.2)
  line L2 (60.8, 11) -> (63, 11)
  line L3 (60.8, 3.5) -> (60.8, 11)
  line L4 (43.8, 0) -> (57.3, 0)
  line L5 (5, 42.6) -> (0, 42.6)
  line L6 (5, 43.8) -> (5, 42.6)
  line L7 (-14.4017, 43.8) -> (5, 43.8)
  line L8 (-26.8692, 39.447) -> (-17.3111, 43.2793)
  line L9 (-15.4823, 5.6727) -> (-27.9812, 36.8463)
  line L10 (11.4211, -2.2) -> (2.3778, -2.2)
  line L11 (61, -2.2) -> (11.4211, -2.2)
  line L12 (-6.267, 41.9413) -> (-3.9887, 36.2589)
  line L13 (-6.2374, 41.9413) -> (-6.267, 41.9413)
  arc A1 centre (61, -0.2) radius 2 clockwise from (63, -0.2) to (61, -2.2)
  arc A2 centre (54.6577, 6.1423) radius 6.6865 clockwise from (60.8, 3.5) to (57.3, 0)
  arc A3 centre (49.0833, 49.2491) radius 49.5316 clockwise from (43.8, 0) to (0, 42.6)
  arc A4 centre (-14.4017, 35.3) radius 8.5 clockwise from (-17.0909, 43.3634) to (-14.4017, 43.8)
  arc A5 centre (-14.613, 36.55) radius 7.25 clockwise from (-17.3111, 43.2793) to (-17.0909, 43.3634)
  arc A6 centre (-26.1249, 37.5906) radius 2 clockwise from (-27.9812, 36.8463) to (-26.8692, 39.447)
  arc A7 centre (1.5418, 20.0938) radius 22.3111 clockwise from (-1.2455, -2.0425) to (-15.4823, 5.6727)
  arc A8 centre (2.4211, 40.5698) radius 42.7698 clockwise from (2.3778, -2.2) to (-1.2455, -2.0425)
extrude "Extrude28" cut of existing geometry blind -2
delete_face "DeleteFace2"
delete_face "DeleteFace3"
extrude "Extrude29" add sketch "Sketch46" profile of A1 L1 L2 L3 A2 L4 A3 L5 L6 L7 A4 A5 L8 A6 L9 A7 A8 L10 L11 against normal blind 2
fillet "Fillet10" radius 1

design "Jeep_Right_Side_v2"
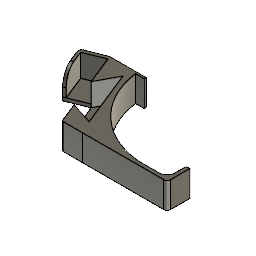
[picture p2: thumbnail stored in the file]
sketch "Sketch1" plane through (0, 0, 0) normal (0, 0, 1) x axis (1, 0, 0)
  line L1 (56, 0) -> (0, 0)
  line L2 (0, 1.2) -> (56, 1.2)
  line L3 (0, 0) -> (0, 1.2)
  line L4 (-1.2, 1.2) -> (0, 1.2)
  line L5 (-1.2, -43.8) -> (-1.2, 1.2)
  line L6 (0, -43.8) -> (-1.2, -43.8)
  line L7 (0, 1.2) -> (0, -43.8)
  line L8 (5, -43.8) -> (0, -43.8)
  line L9 (5, -42.6) -> (5, -43.8)
  line L10 (0, -42.6) -> (5, -42.6)
  line L11 (0, -43.8) -> (0, -42.6)
  line L12 (54.8, 0) -> (56, 0)
  line L13 (61, 1.2) -> (56, 1.2)
  line L14 (56, 0) -> (61, 0)
  line L15 (59.8, 0) -> (61, 0)
  line L16 (62, 1.2) -> (61, 1.2)
  line L17 (62, 0) -> (62, 1.2)
  line L18 (61, 0) -> (62, 0)
  line L19 (60.8, 0) -> (62, 0)
  line L20 (40.8, 0) -> (60.8, 0)
  line L21 (14.1421, -14.1421) -> (0, 0)
  line L22 (43.8, 0) -> (60.8, 0)
  line L23 (60.8, 0) -> (62, 0)
  line L24 (60.8, -13) -> (60.8, 0)
  line L25 (62, -13) -> (60.8, -13)
  line L26 (62, 0) -> (62, -13)
  line L27 (58.8, 0) -> (60.8, 0)
  line L28 (60.8, -2) -> (60.8, 0)
  line L29 (59.3858, -1.4142) -> (60.8, 0)
  line L30 (62.8, 0) -> (60.8, 0)
  line L31 (57.3, 0) -> (60.8, 0)
  line L32 (60.8, -3.5) -> (60.8, 0)
  line L33 (57.3, 0) -> (60.8, 0)
  line L34 (62, -11) -> (62, -13)
  line L35 (60.8, -11) -> (62, -11)
  arc A1 centre (49.0833, -49.2491) radius 49.5316 clockwise from (0, -42.6) to (43.8, 0)
  arc A2 centre (49.0833, -49.2491) radius 50.7316 clockwise from (-1.1891, -42.4389) to (43.672, 1.1932)
  arc A3 centre (54.6577, -6.1423) radius 6.6865 clockwise from (57.3, 0) to (60.8, -3.5)
  point P1 (0, 0)
  point P2 (0, 0)
  point P22 (0, 0)
  point P23 (14.1421, -14.1421)
  point P33 (60.8, -2)
  point P36 (57.3, 0)
  point P34 (59.3858, -1.4142)
  point P41 (60.8, -11)
  point P5 (0, 1.2)
  point P6 (-1.2, 1.2)
  point P8 (0, -43.8)
  point P9 (5, -43.8)
  point P11 (0, -42.6)
  point P13 (61, 1.2)
  point P17 (62, 1.2)
  point P20 (60.8, 0)
  point P24 (43.8, 0)
  point P18 (62, 0)
  point P31 (62, -13)
  point P29 (60.8, 0)
  point P37 (60.8, -3.5)
  point P38 (57.3, 0)
  point P40 (62, -11)
  horizontal L1
  horizontal L2
  vertical L3
  coincident P1 P2
  horizontal L4
  vertical L5
  horizontal L6
  vertical L7
  horizontal L8
  vertical L9
  horizontal L10
  vertical L11
  horizontal L12
  horizontal L13
  horizontal L14
  horizontal L15
  horizontal L16
  vertical L17
  horizontal L18
  horizontal L19
  coincident P1 P22
  coincident P23 A1
  horizontal L23
  vertical L24
  horizontal L25
  vertical L26
  coincident L24 P33
  perpendicular L18 L28
  horizontal L30
  coincident L14 P36
  coincident L22 P36
  coincident L20 P36
  coincident P34 A3
  coincident L24 P41
  perpendicular L24 L35
  dimension "d26" distance P2 P5 = 1.2
  dimension "d27" distance P5 P6 = 1.2
  dimension "d28" distance P5 P8 = 45
  dimension "d29" distance P8 P9 = 5
  dimension "d30" distance P8 P11 = 1.2
  dimension "d34" distance P13 P17 = 1
  dimension "d38" distance P22 P23 = 20
  dimension "d39" distance P20 P24 = 17
  dimension "d40" = 1.2
  dimension "d41" distance P18 P31 = 13
  dimension "d42" distance P18 P29 = 1.2
  dimension "d45" angle L29 L30 = 135
  dimension "d46" distance P29 P34 = 2
  dimension "d47" distance P20 P37 = 3.5
  dimension "d48" distance P29 P38 = 3.5
  dimension "d49" distance P31 P40 = 2
extrude "Extrude1" new body sketch "Sketch1" profile of L1 L2 L3 L4 L5 L6 L7 L8 L9 L10 L11 L12 L13 L14 L15 L16 L17 L18 L19 L20 L21 L22 A1 A2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 along normal blind 5
sketch "Sketch2" plane through (0, 0, 0) normal (0, 0, 1) x axis (1, 0, 0)
  line L1 (5, -43.8) -> (-1.2, -43.8)
  line L2 (36.9084, 0) -> (0, 0)
  line L3 (-3.5615, -43.8) -> (14.2717, 0)
  line L4 (-4.6753, -43.3534) -> (-3.5615, -43.8)
  line L5 (12.7071, 0) -> (-4.6753, -43.3534)
  line L6 (-1.2, -43.8) -> (-3.5615, -43.8)
  line L7 (-9.9836, -40.5566) -> (-4.6753, -43.3534)
  line L8 (-5.7884, -32.5942) -> (-9.9836, -40.5566)
  line L9 (-1.3079, -34.9548) -> (-5.7884, -32.5942)
  line L10 (9.3578, -8.3536) -> (12.7071, 0)
  line L11 (3.7888, -6.1207) -> (9.3578, -8.3536)
  line L12 (6.2428, 0) -> (3.7888, -6.1207)
  line L13 (-1.2, -38) -> (-1.2, -43.8)
  line L14 (-3.5615, -43.8) -> (-1.2, -38)
  point P7 (14.2717, 0)
  point P10 (12.7071, 0)
  point P3 (-1.2, -43.8)
  point P11 (-1.2, -43.8)
  point P14 (-1.3079, -34.9548)
  point P17 (6.2428, 0)
  point P18 (-1.2, -38)
  point P8 (-3.5615, -43.8)
  point P9 (-4.6753, -43.3534)
  point P12 (-9.9836, -40.5566)
  point P13 (-5.7884, -32.5942)
  point P15 (9.3578, -8.3536)
  point P16 (3.7888, -6.1207)
  coincident L2 P7
  coincident L2 P10
  perpendicular L4 L5
  coincident P3 P11
  parallel L1 L6
  coincident L5 P14
  perpendicular L8 L9
  coincident L2 P17
  perpendicular L11 L12
  coincident L3 P18
  perpendicular L1 L13
  dimension "d52" distance P8 P9 = 1.2
  dimension "d55" distance P9 P12 = 6
  dimension "d56" distance P12 P13 = 9
  dimension "d57" distance P10 P15 = 9
  dimension "d58" distance P15 P16 = 6
extrude "Extrude2" add sketch "Sketch2" profile of L2 L3 L4 L5 L6 L7 L8 L9 L10 L11 L12 L13 L14 along normal blind 15
extrude "Extrude3" add of existing geometry blind 10
sketch "Sketch3" plane through (0, 0, 15) normal (0, 0, 1) x axis (-1, 0, 0)
  line L1 (-14.2717, 0) -> (0, 35.0527)
  line L2 (-36.9084, 0) -> (-14.2717, 0)
  line L3 (0, 35.0527) -> (0, 36.4223)
  line L4 (-3.7888, 6.1207) -> (-6.2428, 0)
  line L5 (-9.3578, 8.3536) -> (-3.7888, 6.1207)
  line L6 (0, 31.6928) -> (-9.3578, 8.3536)
  line L7 (0, 0) -> (0, 31.6928)
  line L8 (-6.2428, 0) -> (0, 0)
  line L9 (-5, 43.8) -> (3.5615, 43.8)
  line L10 (-5, 42.6) -> (-5, 43.8)
  line L11 (0, 42.6) -> (-5, 42.6)
  line L12 (-57.3, 0) -> (-43.8, 0)
  line L13 (-60.8, 11) -> (-60.8, 3.5)
  line L14 (-62, 11) -> (-60.8, 11)
  line L15 (-62, -1.2) -> (-62, 11)
  line L16 (1.2, -1.2) -> (-62, -1.2)
  line L17 (1.2, 34.6857) -> (1.2, -1.2)
  line L18 (1.3079, 34.9548) -> (1.2, 34.6857)
  line L19 (5.7884, 32.5942) -> (1.3079, 34.9548)
  line L20 (9.9836, 40.5566) -> (5.7884, 32.5942)
  line L21 (4.6753, 43.3534) -> (9.9836, 40.5566)
  line L22 (3.5615, 43.8) -> (4.6753, 43.3534)
  line L23 (1.2, 34.6857) -> (0, 31.6928)
  line L24 (-7.3301, -2.7117) -> (-5.8415, 1.001)
  arc A1 centre (-49.0833, 49.2491) radius 50.7316 clockwise from (0, 36.4223) to (-36.9084, 0)
  arc A2 centre (-49.0833, 49.2491) radius 49.5316 clockwise from (0, 42.6) to (-43.8, 0)
  arc A3 centre (-54.6577, 6.1423) radius 6.6865 clockwise from (-57.3, 0) to (-60.8, 3.5)
  point P10 (0, 31.6928)
  point P29 (0, 31.6928)
  point P24 (1.2, 34.6857)
  point P30 (1.2, 34.6857)
  point P31 (-5.8415, 1.001)
  point P32 (-7.3301, -2.7117)
  coincident P10 P29
  coincident P24 P30
  coincident L4 P31
  dimension "d63" distance P31 P32 = 4
extrude "Extrude4" cut sketch "Sketch3" profile of L7 L8 L16 L17 L23 L24 against normal blind 19
sketch "Sketch4" plane through (0, 0, 0) normal (0, 0, 1) x axis (1, 0, 0)
sketch "Sketch5" plane through (0, 0, 0) normal (0, 0, 1) x axis (1, 0, 0)
  line L1 (36.9084, 0) -> (14.2717, 0)
  line L2 (36.9084, 0) -> (14.2717, 0)
  line L3 (0, -35.0527) -> (14.2717, 0)
  line L4 (0, -36.4223) -> (0, -35.0527)
  arc A1 centre (49.0833, -49.2491) radius 50.7316 clockwise from (0, -36.4223) to (36.9084, 0)
  arc A2 centre (49.0833, -49.2491) radius 50.7316 clockwise from (0, -36.4223) to (36.9084, 0)
  point P2 (14.2717, 0)
  point P6 (14.2717, 0)
  point P3 (36.9084, 0)
  point P7 (36.9084, 0)
  point P9 (36.9084, 0)
  point P8 (0, -36.4223)
  point P11 (0, -36.4223)
  point P14 (0, -35.0527)
  point P15 (0, -35.0527)
  point P12 (0, -36.4223)
  point P16 (0, -36.4223)
  coincident P2 P6
  coincident P3 P7
  coincident P3 P9
  coincident P8 P11
  coincident P14 P15
  coincident P12 P16
extrude "Extrude5" add sketch "Sketch5" along normal blind 15
sketch "Sketch6" plane through (0, 0, 0) normal (0, 0, 1) x axis (1, 0, 0)
extrude "Extrude6" add of existing geometry blind 1
fillet "Fillet1" radius 2.5
fillet "Fillet2" radius 3
sketch "Sketch7" plane through (0, 0, 15) normal (0, 0, 1) x axis (-1, 0, 0)
  line L1 (-8.724, -2.2) -> (-59, -2.2)
  line L2 (-3.7888, 6.1207) -> (-6.724, -1.2)
  line L3 (-9.3578, 8.3536) -> (-3.7888, 6.1207)
  line L4 (1.3079, 34.9548) -> (-9.3578, 8.3536)
  line L5 (5.7884, 32.5942) -> (1.3079, 34.9548)
  line L6 (9.9836, 40.5566) -> (5.7884, 32.5942)
  line L7 (4.6753, 43.3534) -> (9.9836, 40.5566)
  line L8 (3.5615, 43.8) -> (4.6753, 43.3534)
  line L9 (-5, 43.8) -> (3.5615, 43.8)
  line L10 (-5, 42.6) -> (-5, 43.8)
  line L11 (0, 42.6) -> (-5, 42.6)
  line L12 (-57.3, 0) -> (-43.8, 0)
  line L13 (-60.8, 11) -> (-60.8, 3.5)
  line L14 (-62, 11) -> (-60.8, 11)
  line L15 (-62, 0.8) -> (-62, 11)
  line L16 (-15.2943, -6.4527) -> (-7.555, 12.8499)
  line L17 (6.3033, 47.414) -> (-1.0507, 29.0723)
  arc A1 centre (-59, 0.8) radius 3 clockwise from (-59, -2.2) to (-62, 0.8)
  arc A2 centre (-8.724, 0.3) radius 2.5 clockwise from (-6.724, -1.2) to (-8.724, -2.2)
  arc A3 centre (-49.0833, 49.2491) radius 49.5316 clockwise from (0, 42.6) to (-43.8, 0)
  arc A4 centre (-54.6577, 6.1423) radius 6.6865 clockwise from (-57.3, 0) to (-60.8, 3.5)
  point P25 (-7.555, 12.8499)
  point P27 (-1.0507, 29.0723)
  coincident L4 P25
  parallel L4 L16
  coincident L4 P27
  parallel L4 L17
extrude "Extrude7" cut sketch "Sketch7" profile of L1 A2 L2 L3 L5 L6 L7 L16 L17 against normal blind 55
sketch "Sketch8" plane through (0, 0, 15) normal (0, 0, 1) x axis (-1, 0, 0)
  line L1 (4.6753, 43.3534) -> (-13.5892, -2.2)
  line L2 (3.5615, 43.8) -> (4.6753, 43.3534)
  line L3 (-5, 43.8) -> (3.5615, 43.8)
  line L4 (-5, 42.6) -> (-5, 43.8)
  line L5 (0, 42.6) -> (-5, 42.6)
  line L6 (-57.3, 0) -> (-43.8, 0)
  line L7 (-60.8, 11) -> (-60.8, 3.5)
  line L8 (-62, 11) -> (-60.8, 11)
  line L9 (-62, 0.8) -> (-62, 11)
  line L10 (-13.5892, -2.2) -> (-59, -2.2)
  line L11 (9.3161, 41.4927) -> (4.6753, 43.3534)
  line L12 (6.339, 34.0673) -> (9.3161, 41.4927)
  line L13 (1.9508, 38.1593) -> (6.339, 34.0673)
  line L14 (12.339, 34.0673) -> (6.339, 34.0673)
  line L15 (-9.142, -4.5438) -> (7.8275, 37.78)
  line L16 (-8.2023, -2.2) -> (-13.5892, -2.2)
  line L17 (-5.2251, 5.2254) -> (-8.2023, -2.2)
  line L18 (-12.6359, 5.303) -> (-5.2251, 5.2254)
  line L19 (2.1861, 5.2254) -> (-5.2251, 5.2254)
  line L20 (13, 43.8) -> (3.5615, 43.8)
  line L21 (11.1769, 46.1335) -> (9.3161, 41.4927)
  arc A1 centre (-49.0833, 49.2491) radius 49.5316 clockwise from (0, 42.6) to (-43.8, 0)
  arc A2 centre (-54.6577, 6.1423) radius 6.6865 clockwise from (-57.3, 0) to (-60.8, 3.5)
  arc A3 centre (-59, 0.8) radius 3 clockwise from (-59, -2.2) to (-62, 0.8)
  point P3 (4.6753, 43.3534)
  point P18 (4.6753, 43.3534)
  point P23 (7.8275, 37.78)
  point P2 (-13.5892, -2.2)
  point P25 (-13.5892, -2.2)
  point P26 (-8.2023, -2.2)
  point P4 (3.5615, 43.8)
  point P30 (3.5615, 43.8)
  point P19 (9.3161, 41.4927)
  point P20 (6.339, 34.0673)
  point P21 (1.9508, 38.1593)
  point P27 (-5.2251, 5.2254)
  point P32 (11.1769, 46.1335)
  coincident P3 P18
  horizontal L14
  midpoint L12 P23
  parallel L12 L15
  coincident P2 P25
  coincident L15 P26
  parallel L10 L16
  horizontal L19
  coincident P4 P30
  parallel L3 L20
  dimension "d75" distance P18 P19 = 5
  dimension "d76" distance P19 P20 = 8
  dimension "d77" angle L13 L14 = 137
  dimension "d78" distance P20 P21 = 6
  dimension "d79" distance P26 P27 = 8
  dimension "d80" angle L18 L19 = 179.4
  dimension "d81" distance P19 P32 = 5
extrude "Extrude8" add sketch "Sketch8" profile of L1 L2 L11 L12 L13 L15 L16 L17 L18 L20 L21 against normal blind 15
sketch "Sketch9" plane through (0, 0, 15) normal (0, 0, 1) x axis (-1, 0, 0)
  line L1 (2.418, 37.7236) -> (-10.5895, 5.2816)
  line L2 (6.339, 34.0673) -> (2.418, 37.7236)
  line L3 (10.2413, 43.8) -> (6.339, 34.0673)
  line L4 (-5, 43.8) -> (10.2413, 43.8)
  line L5 (-5, 42.6) -> (-5, 43.8)
  line L6 (0, 42.6) -> (-5, 42.6)
  line L7 (-57.3, 0) -> (-43.8, 0)
  line L8 (-60.8, 11) -> (-60.8, 3.5)
  line L9 (-62, 11) -> (-60.8, 11)
  line L10 (-62, 0.8) -> (-62, 11)
  line L11 (-8.2023, -2.2) -> (-59, -2.2)
  line L12 (-5.2251, 5.2254) -> (-8.2023, -2.2)
  line L13 (-10.5895, 5.2816) -> (-5.2251, 5.2254)
  line L14 (-5.9624, 11.4479) -> (-7.8187, 12.1922)
  line L15 (-11.4084, -2.1682) -> (-5.9624, 11.4479)
  line L16 (8.7025, 11.4479) -> (-5.9624, 11.4479)
  line L17 (8.6956, 47.9984) -> (-7.264, 8.1935)
  line L18 (-11.5321, -2.4773) -> (-11.3387, -1.9939)
  arc A1 centre (-49.0833, 49.2491) radius 49.5316 clockwise from (0, 42.6) to (-43.8, 0)
  arc A2 centre (-54.6577, 6.1423) radius 6.6865 clockwise from (-57.3, 0) to (-60.8, 3.5)
  arc A3 centre (-59, 0.8) radius 3 clockwise from (-59, -2.2) to (-62, 0.8)
  point P21 (-7.8187, 12.1922)
  point P25 (-7.264, 8.1935)
  point P27 (-11.3387, -1.9939)
  point P22 (-5.9624, 11.4479)
  coincident L1 P21
  horizontal L16
  coincident L15 P25
  parallel L1 L17
  coincident L15 P27
  parallel L15 L18
  dimension "d84" distance P21 P22 = 2
  dimension "d85" angle L15 L16 = 111.8
extrude "Extrude9" cut sketch "Sketch9" profile of L2 L3 L4 L11 L12 L13 L15 L17 L18 against normal blind 20
sketch "Sketch10" plane through (0, 0, 15) normal (0, 0, 1) x axis (-1, 0, 0)
  line L1 (-8.4377, 5.259) -> (-11.4211, -2.2)
  line L2 (-10.5895, 5.2816) -> (-8.4377, 5.259)
  line L3 (2.418, 37.7236) -> (-10.5895, 5.2816)
  line L4 (3.9887, 36.2589) -> (2.418, 37.7236)
  line L5 (7.0123, 43.8) -> (3.9887, 36.2589)
  line L6 (-5, 43.8) -> (7.0123, 43.8)
  line L7 (-5, 42.6) -> (-5, 43.8)
  line L8 (0, 42.6) -> (-5, 42.6)
  line L9 (-57.3, 0) -> (-43.8, 0)
  line L10 (-60.8, 11) -> (-60.8, 3.5)
  line L11 (-62, 11) -> (-60.8, 11)
  line L12 (-62, 0.8) -> (-62, 11)
  line L13 (-11.4211, -2.2) -> (-59, -2.2)
  line L14 (7.1686, 14.1022) -> (-5.0833, 19.0145)
  line L15 (25.776, 60.5109) -> (7.1686, 14.1022)
  line L16 (-11.4388, -32.3065) -> (7.1686, 14.1022)
  line L17 (9, -2.2) -> (-11.4211, -2.2)
  line L18 (57.0123, 43.8) -> (7.0123, 43.8)
  line L19 (34.8575, 32.6356) -> (7.0123, 43.8)
  arc A1 centre (-49.0833, 49.2491) radius 49.5316 clockwise from (0, 42.6) to (-43.8, 0)
  arc A2 centre (-54.6577, 6.1423) radius 6.6865 clockwise from (-57.3, 0) to (-60.8, 3.5)
  arc A3 centre (-59, 0.8) radius 3 clockwise from (-59, -2.2) to (-62, 0.8)
  point P21 (-5.0833, 19.0145)
  point P2 (-11.4211, -2.2)
  point P25 (-11.4211, -2.2)
  point P7 (7.0123, 43.8)
  point P27 (7.0123, 43.8)
  point P22 (7.1686, 14.1022)
  point P23 (25.776, 60.5109)
  point P24 (-11.4388, -32.3065)
  point P28 (57.0123, 43.8)
  point P29 (34.8575, 32.6356)
  coincident L3 P21
  coincident P2 P25
  parallel L13 L17
  coincident P7 P27
  dimension "d88" distance P21 P22 = 13.2
  dimension "d89" distance P22 P23 = 50
  dimension "d90" distance P22 P24 = 50
  dimension "d91" distance P27 P28 = 50
  dimension "d92" distance P27 P29 = 30
extrude "Extrude10" new body sketch "Sketch10" profile of L1 L2 L3 L4 L5 L14 L15 L16 L17 L19 along normal blind 2
move "Move1"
